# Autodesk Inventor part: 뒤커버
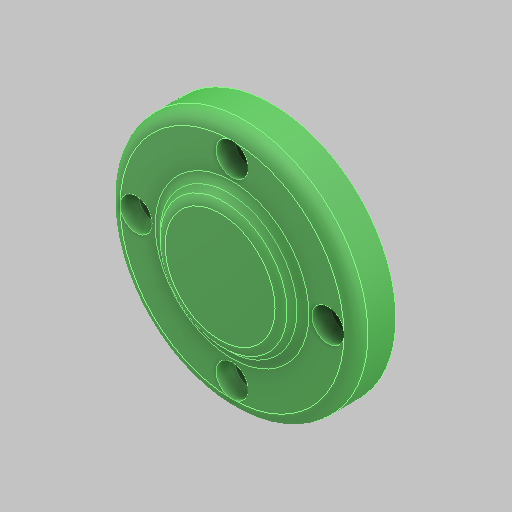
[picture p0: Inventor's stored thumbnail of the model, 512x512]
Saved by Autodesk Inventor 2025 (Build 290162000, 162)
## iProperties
Created: 2024-07
Part Number: 뒤커버
Material: 알루미늄 6061
Document SubType Name: Modeling
Designer: 현기
Density: 2.71 g/cm^3
Appearance: 기본값
Author: jhkim
Sending System: Autodesk Inventor 2025
Preprocessor: ST-DEVELOPER v20
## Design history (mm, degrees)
feature "솔리드1"
node "솔리드2"
